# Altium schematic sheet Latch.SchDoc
size B
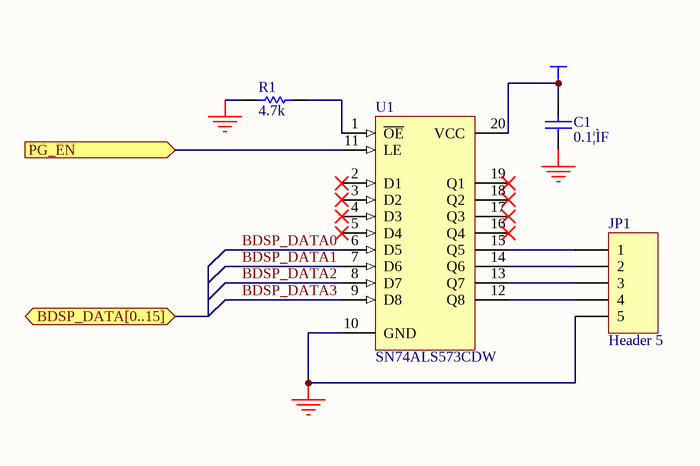
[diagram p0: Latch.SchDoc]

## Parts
C1  0.1¦ÌF  [RAD-0.3]
JP1  Header 5  [HDR1X5]
R1  4.7k  [AXIAL-0.3]
U1  SN74ALS573CDW  [SO-G20/G7.1]

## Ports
BDSP_DATA[0..15] (bidir), PG_EN (in)

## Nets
GND: C1.1 JP1.5 R1.1 U1.10(GND)
VCC: C1.2 U1.20(VCC)
BDSP_DATA0: U1.6(D5)
BDSP_DATA1: U1.7(D6)
BDSP_DATA2: U1.8(D7)
BDSP_DATA3: U1.9(D8)
PG_EN: U1.11(LE) ; port PG_EN
NetJP1_1: JP1.1 U1.15(Q5)
NetJP1_2: JP1.2 U1.14(Q6)
NetJP1_3: JP1.3 U1.13(Q7)
NetJP1_4: JP1.4 U1.12(Q8)
NetR1_2: R1.2 U1.1(~{OE})

Not connected (* = marked no-connect by the designer): U1 2(D1)* 3(D2)* 4(D3)* 5(D4)* 16(Q4)* 17(Q3)* 18(Q2)* 19(Q1)*

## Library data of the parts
C1 = Cap: Capacitor; Manufacturer: Generic Components; Class I: Passive
JP1 = Header 5: Header, 5-Pin; Manufacturer: Generic Components; Class I: Connector
R1 = Res1: Resistor; Manufacturer: Generic Components; Class I: Passive; Value: 1K
U1 = SN74ALS573CDW: Octal D-Type Transparent Latches with 3-State Outputs; Manufacturer: Texas Instruments; Package Information: Latest Revision: Dec-1998; Class I: Logic; Class II: Latch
